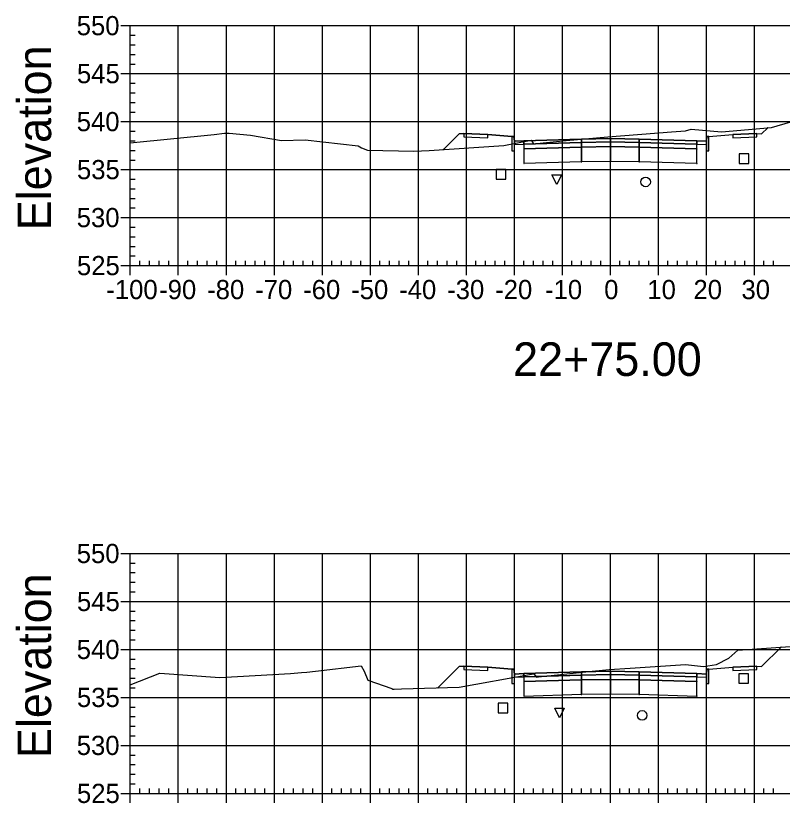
# Model space of a CAD drawing. Extents: x 704834 to 709892, y 372981 to 377533.
# Drawn here: x 707731 to 707890.7, y 376148.8 to 376312.9 of the extents above; entities that cross this region are included whole.
import ezdxf

# ---------------------------------------------------------------- set-up
doc = ezdxf.new("R2010")
doc.units = 0
for name, color, linetype in [('1', 7, 'Continuous'), ('10', 7, 'Continuous'), ('13', 7, 'Continuous'), ('14', 7, 'Continuous'), ('4', 7, 'Continuous'), ('57', 7, 'Continuous'), ('60', 7, 'Continuous'), ('Default_Xsect', 7, 'Continuous'), ('Existing', 7, 'Continuous')]:
    doc.layers.add(name, color=color, linetype=linetype)

msp = doc.modelspace()

# ---------------------------------------------------------------- linework, layer by layer
for points in [[(707886.41, 376288.28), (707887.69, 376289.55)], [(707823.41, 376288.28), (707820.13, 376285)], [(707824.41, 376288.32), (707823.41, 376288.28)], [(707834.41, 376287.72), (707829.41, 376288.12)], [(707875.41, 376287.72), (707880.41, 376288.12)], [(707885.41, 376288.32), (707886.41, 376288.28)], [(707886.41, 376177.26), (707890.47, 376181.31)], [(707823.41, 376177.26), (707818.99, 376172.84)], [(707824.41, 376177.3), (707823.41, 376177.26)], [(707834.41, 376176.7), (707829.41, 376177.1)], [(707875.41, 376176.7), (707880.41, 376177.1)], [(707885.41, 376177.3), (707886.41, 376177.26)]]:
    msp.add_lwpolyline(points)
for points in [[(707829.41, 376288.12), (707824.41, 376288.32), (707824.41, 376287.65), (707829.41, 376287.45)], [(707834.91, 376286.72), (707834.83, 376287.72), (707834.41, 376287.72), (707834.41, 376284.72), (707834.91, 376284.72)], [(707874.91, 376284.72), (707875.41, 376284.72), (707875.41, 376287.72), (707875, 376287.72), (707874.91, 376286.72)], [(707880.41, 376287.45), (707885.41, 376287.65), (707885.41, 376288.32), (707880.41, 376288.12)], [(707836.91, 376286.8), (707834.91, 376286.72), (707834.91, 376286.05), (707836.91, 376286.13)], [(707848.91, 376287.16), (707836.91, 376286.8), (707836.91, 376286.13), (707848.91, 376286.49)], [(707848.91, 376286.49), (707836.91, 376286.13), (707836.91, 376285.13), (707848.91, 376285.49)], [(707848.86, 376286.44), (707848.96, 376286.44), (707848.96, 376286.54), (707848.86, 376286.54)], [(707854.91, 376287.28), (707848.91, 376287.16), (707848.91, 376286.49), (707854.91, 376286.61)], [(707854.91, 376286.61), (707848.91, 376286.49), (707848.91, 376285.49), (707854.91, 376285.61)], [(707854.86, 376286.56), (707854.96, 376286.56), (707854.96, 376286.66), (707854.86, 376286.66)], [(707854.91, 376286.61), (707860.91, 376286.49), (707860.91, 376287.16), (707854.91, 376287.28)], [(707854.91, 376285.61), (707860.91, 376285.49), (707860.91, 376286.49), (707854.91, 376286.61)], [(707860.86, 376286.44), (707860.96, 376286.44), (707860.96, 376286.54), (707860.86, 376286.54)], [(707860.91, 376286.49), (707872.91, 376286.13), (707872.91, 376286.8), (707860.91, 376287.16)], [(707860.91, 376285.49), (707872.91, 376285.13), (707872.91, 376286.13), (707860.91, 376286.49)], [(707872.91, 376286.13), (707874.91, 376286.05), (707874.91, 376286.72), (707872.91, 376286.8)], [(707836.86, 376285.08), (707836.96, 376285.08), (707836.96, 376285.18), (707836.86, 376285.18)], [(707848.91, 376285.49), (707836.91, 376285.13), (707836.91, 376282.13), (707848.91, 376282.49)], [(707848.86, 376285.44), (707848.96, 376285.44), (707848.96, 376285.54), (707848.86, 376285.54)], [(707854.91, 376285.61), (707848.91, 376285.49), (707848.91, 376282.49), (707854.91, 376282.61)], [(707854.86, 376285.56), (707854.96, 376285.56), (707854.96, 376285.66), (707854.86, 376285.66)], [(707854.91, 376282.61), (707860.91, 376282.49), (707860.91, 376285.49), (707854.91, 376285.61)], [(707860.86, 376285.44), (707860.96, 376285.44), (707860.96, 376285.54), (707860.86, 376285.54)], [(707860.91, 376282.49), (707872.91, 376282.13), (707872.91, 376285.13), (707860.91, 376285.49)], [(707872.86, 376285.08), (707872.96, 376285.08), (707872.96, 376285.18), (707872.86, 376285.18)], [(707836.86, 376282.08), (707836.96, 376282.08), (707836.96, 376282.18), (707836.86, 376282.18)], [(707848.86, 376282.44), (707848.96, 376282.44), (707848.96, 376282.54), (707848.86, 376282.54)], [(707854.86, 376282.56), (707854.96, 376282.56), (707854.96, 376282.66), (707854.86, 376282.66)], [(707860.86, 376282.44), (707860.96, 376282.44), (707860.96, 376282.54), (707860.86, 376282.54)], [(707872.86, 376282.08), (707872.96, 376282.08), (707872.96, 376282.18), (707872.86, 376282.18)], [(707829.41, 376177.1), (707824.41, 376177.3), (707824.41, 376176.63), (707829.41, 376176.43)], [(707834.91, 376175.7), (707834.83, 376176.7), (707834.41, 376176.7), (707834.41, 376173.7), (707834.91, 376173.7)], [(707848.91, 376176.14), (707836.91, 376175.78), (707836.91, 376175.11), (707848.91, 376175.47)], [(707854.91, 376176.26), (707848.91, 376176.14), (707848.91, 376175.47), (707854.91, 376175.59)], [(707854.91, 376175.59), (707860.91, 376175.47), (707860.91, 376176.14), (707854.91, 376176.26)], [(707860.91, 376175.47), (707872.91, 376175.11), (707872.91, 376175.78), (707860.91, 376176.14)], [(707874.91, 376173.7), (707875.41, 376173.7), (707875.41, 376176.7), (707875, 376176.7), (707874.91, 376175.7)], [(707880.41, 376176.43), (707885.41, 376176.63), (707885.41, 376177.3), (707880.41, 376177.1)], [(707836.91, 376175.78), (707834.91, 376175.7), (707834.91, 376175.03), (707836.91, 376175.11)], [(707848.91, 376175.47), (707836.91, 376175.11), (707836.91, 376174.11), (707848.91, 376174.47)], [(707848.91, 376174.47), (707836.91, 376174.11), (707836.91, 376171.11), (707848.91, 376171.47)], [(707848.86, 376175.42), (707848.96, 376175.42), (707848.96, 376175.52), (707848.86, 376175.52)], [(707848.86, 376174.42), (707848.96, 376174.42), (707848.96, 376174.52), (707848.86, 376174.52)], [(707854.91, 376175.59), (707848.91, 376175.47), (707848.91, 376174.47), (707854.91, 376174.59)], [(707854.91, 376174.59), (707848.91, 376174.47), (707848.91, 376171.47), (707854.91, 376171.59)], [(707854.86, 376175.54), (707854.96, 376175.54), (707854.96, 376175.64), (707854.86, 376175.64)], [(707854.86, 376174.54), (707854.96, 376174.54), (707854.96, 376174.64), (707854.86, 376174.64)], [(707854.91, 376174.59), (707860.91, 376174.47), (707860.91, 376175.47), (707854.91, 376175.59)], [(707854.91, 376171.59), (707860.91, 376171.47), (707860.91, 376174.47), (707854.91, 376174.59)], [(707860.86, 376175.42), (707860.96, 376175.42), (707860.96, 376175.52), (707860.86, 376175.52)], [(707860.86, 376174.42), (707860.96, 376174.42), (707860.96, 376174.52), (707860.86, 376174.52)], [(707860.91, 376174.47), (707872.91, 376174.11), (707872.91, 376175.11), (707860.91, 376175.47)], [(707860.91, 376171.47), (707872.91, 376171.11), (707872.91, 376174.11), (707860.91, 376174.47)], [(707872.91, 376175.11), (707874.91, 376175.03), (707874.91, 376175.7), (707872.91, 376175.78)], [(707836.86, 376174.06), (707836.96, 376174.06), (707836.96, 376174.16), (707836.86, 376174.16)], [(707872.86, 376174.06), (707872.96, 376174.06), (707872.96, 376174.16), (707872.86, 376174.16)], [(707848.86, 376171.42), (707848.96, 376171.42), (707848.96, 376171.52), (707848.86, 376171.52)], [(707854.86, 376171.54), (707854.96, 376171.54), (707854.96, 376171.64), (707854.86, 376171.64)], [(707860.86, 376171.42), (707860.96, 376171.42), (707860.96, 376171.52), (707860.86, 376171.52)], [(707836.86, 376171.06), (707836.96, 376171.06), (707836.96, 376171.16), (707836.86, 376171.16)], [(707872.86, 376171.06), (707872.96, 376171.06), (707872.96, 376171.16), (707872.86, 376171.16)]]:
    msp.add_lwpolyline(points, close=True)
at = {"layer": '1'}
for points in [[(707843.74, 376277.7), (707842.74, 376279.7), (707844.74, 376279.7)], [(707844.31, 376166.56), (707843.31, 376168.56), (707845.31, 376168.56)]]:
    msp.add_lwpolyline(points, close=True, dxfattribs=at)
at = {"layer": '10'}
for points in [[(707831.14, 376278.83), (707833.14, 376278.83), (707833.14, 376280.83), (707831.14, 376280.83)], [(707831.54, 376167.61), (707833.54, 376167.61), (707833.54, 376169.61), (707831.54, 376169.61)]]:
    msp.add_lwpolyline(points, close=True, dxfattribs=at)
at = {"layer": '13'}
for centre in [(707862.25, 376278.25), (707861.53, 376167.07)]:
    msp.add_circle(centre, 1, dxfattribs=at)
at = {"layer": '14'}
for points in [[(707887.69, 376289.55), (707887.69, 376289.6), (707887.69, 376289.55), (707887.64, 376289.55), (707887.69, 376289.55), (707887.69, 376289.5), (707887.69, 376289.55), (707887.74, 376289.55)], [(707836.91, 376286.8), (707836.91, 376286.85), (707836.91, 376286.8), (707836.86, 376286.8), (707836.91, 376286.8), (707836.91, 376286.75), (707836.91, 376286.8), (707836.96, 376286.8)], [(707854.91, 376287.28), (707854.91, 376287.33), (707854.91, 376287.28), (707854.86, 376287.28), (707854.91, 376287.28), (707854.91, 376287.23), (707854.91, 376287.28), (707854.96, 376287.28)], [(707872.91, 376286.8), (707872.91, 376286.85), (707872.91, 376286.8), (707872.86, 376286.8), (707872.91, 376286.8), (707872.91, 376286.75), (707872.91, 376286.8), (707872.96, 376286.8)], [(707820.13, 376285), (707820.13, 376285.05), (707820.13, 376285), (707820.08, 376285), (707820.13, 376285), (707820.13, 376284.95), (707820.13, 376285), (707820.18, 376285)], [(707890.47, 376181.31), (707890.47, 376181.36), (707890.47, 376181.31), (707890.42, 376181.31), (707890.47, 376181.31), (707890.47, 376181.26), (707890.47, 376181.31), (707890.52, 376181.31)], [(707854.91, 376176.26), (707854.91, 376176.31), (707854.91, 376176.26), (707854.86, 376176.26), (707854.91, 376176.26), (707854.91, 376176.21), (707854.91, 376176.26), (707854.96, 376176.26)], [(707836.91, 376175.78), (707836.91, 376175.83), (707836.91, 376175.78), (707836.86, 376175.78), (707836.91, 376175.78), (707836.91, 376175.73), (707836.91, 376175.78), (707836.96, 376175.78)], [(707872.91, 376175.78), (707872.91, 376175.83), (707872.91, 376175.78), (707872.86, 376175.78), (707872.91, 376175.78), (707872.91, 376175.73), (707872.91, 376175.78), (707872.96, 376175.78)], [(707818.99, 376172.84), (707818.99, 376172.89), (707818.99, 376172.84), (707818.94, 376172.84), (707818.99, 376172.84), (707818.99, 376172.79), (707818.99, 376172.84), (707819.04, 376172.84)]]:
    msp.add_lwpolyline(points, dxfattribs=at)
at = {"layer": '4'}
for points in [[(707881.75, 376282.12), (707883.75, 376282.12), (707883.75, 376284.12), (707881.75, 376284.12)], [(707881.66, 376173.77), (707883.66, 376173.77), (707883.66, 376175.77), (707881.66, 376175.77)]]:
    msp.add_lwpolyline(points, close=True, dxfattribs=at)
at = {"layer": '57'}
for p, q in [((707752.91, 376310.82), (707754.91, 376310.82)), ((707754.91, 376310.82), (707954.91, 376310.82)), ((707754.91, 376260.82), (707754.91, 376310.82)), ((707754.91, 376260.82), (707754.91, 376310.82)), ((707764.91, 376260.82), (707764.91, 376310.82)), ((707774.91, 376260.82), (707774.91, 376310.82)), ((707784.91, 376260.82), (707784.91, 376310.82)), ((707794.91, 376260.82), (707794.91, 376310.82)), ((707804.91, 376260.82), (707804.91, 376310.82)), ((707814.91, 376260.82), (707814.91, 376310.82)), ((707824.91, 376260.82), (707824.91, 376310.82)), ((707834.91, 376260.82), (707834.91, 376310.82)), ((707844.91, 376260.82), (707844.91, 376310.82)), ((707854.91, 376260.82), (707854.91, 376310.82)), ((707864.91, 376260.82), (707864.91, 376310.82)), ((707874.91, 376260.82), (707874.91, 376310.82)), ((707884.91, 376260.82), (707884.91, 376310.82)), ((707754.91, 376308.82), (707755.91, 376308.82)), ((707754.91, 376306.82), (707755.91, 376306.82)), ((707754.91, 376304.82), (707755.91, 376304.82)), ((707754.91, 376302.82), (707755.91, 376302.82)), ((707752.91, 376300.82), (707754.91, 376300.82)), ((707754.91, 376300.82), (707954.91, 376300.82)), ((707754.91, 376298.82), (707755.91, 376298.82)), ((707754.91, 376296.82), (707755.91, 376296.82)), ((707754.91, 376294.82), (707755.91, 376294.82)), ((707754.91, 376292.82), (707755.91, 376292.82)), ((707752.91, 376290.82), (707754.91, 376290.82)), ((707754.91, 376290.82), (707954.91, 376290.82)), ((707754.91, 376288.82), (707755.91, 376288.82)), ((707754.91, 376286.82), (707755.91, 376286.82)), ((707754.91, 376284.82), (707755.91, 376284.82)), ((707754.91, 376282.82), (707755.91, 376282.82)), ((707752.91, 376280.82), (707754.91, 376280.82)), ((707754.91, 376280.82), (707954.91, 376280.82)), ((707754.91, 376278.82), (707755.91, 376278.82)), ((707754.91, 376276.82), (707755.91, 376276.82)), ((707754.91, 376274.82), (707755.91, 376274.82)), ((707754.91, 376272.82), (707755.91, 376272.82)), ((707752.91, 376270.82), (707754.91, 376270.82)), ((707754.91, 376270.82), (707954.91, 376270.82)), ((707754.91, 376268.82), (707755.91, 376268.82)), ((707754.91, 376266.82), (707755.91, 376266.82)), ((707754.91, 376264.82), (707755.91, 376264.82)), ((707754.91, 376262.82), (707755.91, 376262.82)), ((707756.91, 376260.82), (707756.91, 376261.82)), ((707758.91, 376260.82), (707758.91, 376261.82)), ((707760.91, 376260.82), (707760.91, 376261.82)), ((707762.91, 376260.82), (707762.91, 376261.82)), ((707766.91, 376260.82), (707766.91, 376261.82)), ((707768.91, 376260.82), (707768.91, 376261.82)), ((707770.91, 376260.82), (707770.91, 376261.82)), ((707772.91, 376260.82), (707772.91, 376261.82)), ((707776.91, 376260.82), (707776.91, 376261.82)), ((707778.91, 376260.82), (707778.91, 376261.82)), ((707780.91, 376260.82), (707780.91, 376261.82)), ((707782.91, 376260.82), (707782.91, 376261.82)), ((707786.91, 376260.82), (707786.91, 376261.82)), ((707788.91, 376260.82), (707788.91, 376261.82)), ((707790.91, 376260.82), (707790.91, 376261.82)), ((707792.91, 376260.82), (707792.91, 376261.82)), ((707796.91, 376260.82), (707796.91, 376261.82)), ((707798.91, 376260.82), (707798.91, 376261.82)), ((707800.91, 376260.82), (707800.91, 376261.82)), ((707802.91, 376260.82), (707802.91, 376261.82)), ((707806.91, 376260.82), (707806.91, 376261.82)), ((707808.91, 376260.82), (707808.91, 376261.82)), ((707810.91, 376260.82), (707810.91, 376261.82)), ((707812.91, 376260.82), (707812.91, 376261.82)), ((707816.91, 376260.82), (707816.91, 376261.82)), ((707818.91, 376260.82), (707818.91, 376261.82)), ((707820.91, 376260.82), (707820.91, 376261.82)), ((707822.91, 376260.82), (707822.91, 376261.82)), ((707826.91, 376260.82), (707826.91, 376261.82)), ((707828.91, 376260.82), (707828.91, 376261.82)), ((707830.91, 376260.82), (707830.91, 376261.82)), ((707832.91, 376260.82), (707832.91, 376261.82)), ((707836.91, 376260.82), (707836.91, 376261.82)), ((707838.91, 376260.82), (707838.91, 376261.82)), ((707840.91, 376260.82), (707840.91, 376261.82)), ((707842.91, 376260.82), (707842.91, 376261.82)), ((707846.91, 376260.82), (707846.91, 376261.82)), ((707848.91, 376260.82), (707848.91, 376261.82)), ((707850.91, 376260.82), (707850.91, 376261.82)), ((707852.91, 376260.82), (707852.91, 376261.82)), ((707856.91, 376260.82), (707856.91, 376261.82)), ((707858.91, 376260.82), (707858.91, 376261.82)), ((707860.91, 376260.82), (707860.91, 376261.82)), ((707862.91, 376260.82), (707862.91, 376261.82)), ((707866.91, 376260.82), (707866.91, 376261.82)), ((707868.91, 376260.82), (707868.91, 376261.82)), ((707870.91, 376260.82), (707870.91, 376261.82)), ((707872.91, 376260.82), (707872.91, 376261.82)), ((707876.91, 376260.82), (707876.91, 376261.82)), ((707878.91, 376260.82), (707878.91, 376261.82)), ((707880.91, 376260.82), (707880.91, 376261.82)), ((707882.91, 376260.82), (707882.91, 376261.82)), ((707886.91, 376260.82), (707886.91, 376261.82)), ((707888.91, 376260.82), (707888.91, 376261.82)), ((707752.91, 376260.82), (707754.91, 376260.82)), ((707754.91, 376260.82), (707954.91, 376260.82)), ((707754.91, 376260.82), (707954.91, 376260.82)), ((707754.91, 376258.82), (707754.91, 376260.82)), ((707764.91, 376258.82), (707764.91, 376260.82)), ((707774.91, 376258.82), (707774.91, 376260.82)), ((707784.91, 376258.82), (707784.91, 376260.82)), ((707794.91, 376258.82), (707794.91, 376260.82)), ((707804.91, 376258.82), (707804.91, 376260.82)), ((707814.91, 376258.82), (707814.91, 376260.82)), ((707824.91, 376258.82), (707824.91, 376260.82)), ((707834.91, 376258.82), (707834.91, 376260.82)), ((707844.91, 376258.82), (707844.91, 376260.82)), ((707854.91, 376258.82), (707854.91, 376260.82)), ((707864.91, 376258.82), (707864.91, 376260.82)), ((707874.91, 376258.82), (707874.91, 376260.82)), ((707884.91, 376258.82), (707884.91, 376260.82)), ((707752.91, 376200.82), (707754.91, 376200.82)), ((707754.91, 376200.82), (707954.91, 376200.82)), ((707754.91, 376150.82), (707754.91, 376200.82)), ((707754.91, 376150.82), (707754.91, 376200.82)), ((707764.91, 376150.82), (707764.91, 376200.82)), ((707774.91, 376150.82), (707774.91, 376200.82)), ((707784.91, 376150.82), (707784.91, 376200.82)), ((707794.91, 376150.82), (707794.91, 376200.82)), ((707804.91, 376150.82), (707804.91, 376200.82)), ((707814.91, 376150.82), (707814.91, 376200.82)), ((707824.91, 376150.82), (707824.91, 376200.82)), ((707834.91, 376150.82), (707834.91, 376200.82)), ((707844.91, 376150.82), (707844.91, 376200.82)), ((707854.91, 376150.82), (707854.91, 376200.82)), ((707864.91, 376150.82), (707864.91, 376200.82)), ((707874.91, 376150.82), (707874.91, 376200.82)), ((707884.91, 376150.82), (707884.91, 376200.82)), ((707754.91, 376198.82), (707755.91, 376198.82)), ((707754.91, 376196.82), (707755.91, 376196.82)), ((707754.91, 376194.82), (707755.91, 376194.82)), ((707754.91, 376192.82), (707755.91, 376192.82)), ((707752.91, 376190.82), (707754.91, 376190.82)), ((707754.91, 376190.82), (707954.91, 376190.82)), ((707754.91, 376188.82), (707755.91, 376188.82)), ((707754.91, 376186.82), (707755.91, 376186.82)), ((707754.91, 376184.82), (707755.91, 376184.82)), ((707754.91, 376182.82), (707755.91, 376182.82)), ((707752.91, 376180.82), (707754.91, 376180.82)), ((707754.91, 376180.82), (707954.91, 376180.82)), ((707754.91, 376178.82), (707755.91, 376178.82)), ((707754.91, 376176.82), (707755.91, 376176.82)), ((707754.91, 376174.82), (707755.91, 376174.82)), ((707754.91, 376172.82), (707755.91, 376172.82)), ((707752.91, 376170.82), (707754.91, 376170.82)), ((707754.91, 376170.82), (707954.91, 376170.82)), ((707754.91, 376168.82), (707755.91, 376168.82)), ((707754.91, 376166.82), (707755.91, 376166.82)), ((707754.91, 376164.82), (707755.91, 376164.82)), ((707754.91, 376162.82), (707755.91, 376162.82)), ((707752.91, 376160.82), (707754.91, 376160.82)), ((707754.91, 376160.82), (707954.91, 376160.82)), ((707754.91, 376158.82), (707755.91, 376158.82)), ((707754.91, 376156.82), (707755.91, 376156.82)), ((707754.91, 376154.82), (707755.91, 376154.82)), ((707754.91, 376152.82), (707755.91, 376152.82)), ((707756.91, 376150.82), (707756.91, 376151.82)), ((707758.91, 376150.82), (707758.91, 376151.82)), ((707760.91, 376150.82), (707760.91, 376151.82)), ((707762.91, 376150.82), (707762.91, 376151.82)), ((707766.91, 376150.82), (707766.91, 376151.82)), ((707768.91, 376150.82), (707768.91, 376151.82)), ((707770.91, 376150.82), (707770.91, 376151.82)), ((707772.91, 376150.82), (707772.91, 376151.82)), ((707776.91, 376150.82), (707776.91, 376151.82)), ((707778.91, 376150.82), (707778.91, 376151.82)), ((707780.91, 376150.82), (707780.91, 376151.82)), ((707782.91, 376150.82), (707782.91, 376151.82)), ((707786.91, 376150.82), (707786.91, 376151.82)), ((707788.91, 376150.82), (707788.91, 376151.82)), ((707790.91, 376150.82), (707790.91, 376151.82)), ((707792.91, 376150.82), (707792.91, 376151.82)), ((707796.91, 376150.82), (707796.91, 376151.82)), ((707798.91, 376150.82), (707798.91, 376151.82)), ((707800.91, 376150.82), (707800.91, 376151.82)), ((707802.91, 376150.82), (707802.91, 376151.82)), ((707806.91, 376150.82), (707806.91, 376151.82)), ((707808.91, 376150.82), (707808.91, 376151.82)), ((707810.91, 376150.82), (707810.91, 376151.82)), ((707812.91, 376150.82), (707812.91, 376151.82)), ((707816.91, 376150.82), (707816.91, 376151.82)), ((707818.91, 376150.82), (707818.91, 376151.82)), ((707820.91, 376150.82), (707820.91, 376151.82)), ((707822.91, 376150.82), (707822.91, 376151.82)), ((707826.91, 376150.82), (707826.91, 376151.82)), ((707828.91, 376150.82), (707828.91, 376151.82)), ((707830.91, 376150.82), (707830.91, 376151.82)), ((707832.91, 376150.82), (707832.91, 376151.82)), ((707836.91, 376150.82), (707836.91, 376151.82)), ((707838.91, 376150.82), (707838.91, 376151.82)), ((707840.91, 376150.82), (707840.91, 376151.82)), ((707842.91, 376150.82), (707842.91, 376151.82)), ((707846.91, 376150.82), (707846.91, 376151.82)), ((707848.91, 376150.82), (707848.91, 376151.82)), ((707850.91, 376150.82), (707850.91, 376151.82)), ((707852.91, 376150.82), (707852.91, 376151.82)), ((707856.91, 376150.82), (707856.91, 376151.82)), ((707858.91, 376150.82), (707858.91, 376151.82)), ((707860.91, 376150.82), (707860.91, 376151.82)), ((707862.91, 376150.82), (707862.91, 376151.82)), ((707866.91, 376150.82), (707866.91, 376151.82)), ((707868.91, 376150.82), (707868.91, 376151.82)), ((707870.91, 376150.82), (707870.91, 376151.82)), ((707872.91, 376150.82), (707872.91, 376151.82)), ((707876.91, 376150.82), (707876.91, 376151.82)), ((707878.91, 376150.82), (707878.91, 376151.82)), ((707880.91, 376150.82), (707880.91, 376151.82)), ((707882.91, 376150.82), (707882.91, 376151.82)), ((707886.91, 376150.82), (707886.91, 376151.82)), ((707888.91, 376150.82), (707888.91, 376151.82)), ((707752.91, 376150.82), (707754.91, 376150.82)), ((707754.91, 376150.82), (707954.91, 376150.82)), ((707754.91, 376150.82), (707954.91, 376150.82)), ((707754.91, 376148.82), (707754.91, 376150.82)), ((707764.91, 376148.82), (707764.91, 376150.82)), ((707774.91, 376148.82), (707774.91, 376150.82)), ((707784.91, 376148.82), (707784.91, 376150.82)), ((707794.91, 376148.82), (707794.91, 376150.82)), ((707804.91, 376148.82), (707804.91, 376150.82)), ((707814.91, 376148.82), (707814.91, 376150.82)), ((707824.91, 376148.82), (707824.91, 376150.82)), ((707834.91, 376148.82), (707834.91, 376150.82)), ((707844.91, 376148.82), (707844.91, 376150.82)), ((707854.91, 376148.82), (707854.91, 376150.82)), ((707864.91, 376148.82), (707864.91, 376150.82)), ((707874.91, 376148.82), (707874.91, 376150.82)), ((707884.91, 376148.82), (707884.91, 376150.82))]:
    msp.add_line(p, q, dxfattribs=at)
at = {"layer": 'Default_Xsect'}
for points in [[(707820.13, 376285), (707823.41, 376288.28), (707824.41, 376288.32), (707829.41, 376288.12), (707834.41, 376287.72), (707834.83, 376287.72), (707834.91, 376286.72), (707836.91, 376286.8), (707848.91, 376287.16), (707854.91, 376287.28), (707860.91, 376287.16), (707872.91, 376286.8), (707874.91, 376286.72), (707875, 376287.72), (707875.41, 376287.72), (707880.41, 376288.12), (707885.41, 376288.32), (707886.41, 376288.28), (707887.69, 376289.55)], [(707818.99, 376172.84), (707823.41, 376177.26), (707824.41, 376177.3), (707829.41, 376177.1), (707834.41, 376176.7), (707834.83, 376176.7), (707834.91, 376175.7), (707836.91, 376175.78), (707848.91, 376176.14), (707854.91, 376176.26), (707860.91, 376176.14), (707872.91, 376175.78), (707874.91, 376175.7), (707875, 376176.7), (707875.41, 376176.7), (707880.41, 376177.1), (707885.41, 376177.3), (707886.41, 376177.26), (707890.47, 376181.31)]]:
    msp.add_lwpolyline(points, dxfattribs=at)
at = {"layer": 'Existing'}
for points in [[(707754.91, 376286.38), (707772.36, 376288.12), (707774.56, 376288.42), (707774.64, 376288.39), (707775.52, 376288.38), (707779.95, 376287.97), (707786.41, 376286.89), (707791.35, 376287.01), (707802.35, 376285.75), (707803.1, 376285.34), (707804.29, 376284.89), (707813.99, 376284.69), (707817.19, 376284.8), (707832.69, 376285.87), (707838.38, 376286.97), (707838.58, 376286.72), (707838.88, 376286.21), (707845.67, 376286.9), (707854.35, 376287.64), (707867.66, 376288.66), (707870.59, 376288.92), (707871.77, 376289.28), (707878.06, 376288.71), (707888.49, 376289.62), (707892.48, 376290.77)], [(707754.91, 376173.46), (707761.04, 376175.86), (707773.54, 376174.96), (707788.27, 376175.81), (707790.6, 376175.99), (707791.67, 376176.11), (707793.45, 376176.31), (707803, 376177.42), (707803.64, 376176.29), (707804.37, 376174.45), (707809.37, 376172.65), (707809.61, 376172.56), (707809.88, 376172.55), (707811.4, 376172.6), (707823.4, 376172.97), (707838.07, 376175.6), (707838.94, 376175.77), (707839.52, 376175.07), (707839.52, 376175.06), (707839.93, 376175.11), (707850.43, 376176.19), (707854.63, 376176.62), (707859.02, 376176.9), (707870.58, 376177.7), (707874.34, 376177.24), (707876.99, 376177.66), (707879.62, 376179), (707881.44, 376180.69), (707896.3, 376181.71)]]:
    msp.add_lwpolyline(points, dxfattribs=at)

# ---------------------------------------------------------------- texts
at = {"layer": '1'}
msp.add_text('22+75.00', height=7, dxfattribs=at).set_placement((707834.64, 376237.82))
at = {"layer": '14'}
for p in [(707824.38, 376288.27), (707885.38, 376288.27), (707824.38, 376287.6), (707829.38, 376287.4), (707880.38, 376287.4), (707885.38, 376287.6), (707824.38, 376177.25), (707824.38, 376176.58), (707829.38, 376176.38), (707880.38, 376176.38), (707885.38, 376177.25), (707885.38, 376176.58)]:
    msp.add_text('+', height=0.1, dxfattribs=at).set_placement(p)
at = {"layer": '57'}
for s, p in [('550', (707743.74, 376308.82)), ('545', (707743.79, 376298.82)), ('540', (707743.74, 376288.82)), ('535', (707743.79, 376278.82)), ('530', (707743.74, 376268.82)), ('525', (707743.79, 376258.82)), ('-100', (707749.9, 376253.82)), ('-90', (707760.91, 376253.82)), ('-80', (707770.91, 376253.82)), ('-70', (707780.91, 376253.82)), ('-60', (707790.91, 376253.82)), ('-50', (707800.91, 376253.82)), ('-40', (707810.91, 376253.82)), ('-30', (707820.91, 376253.82)), ('-20', (707830.91, 376253.82)), ('-10', (707841.3, 376253.82)), ('0', (707853.62, 376253.82)), ('10', (707862.61, 376253.82)), ('20', (707872.22, 376253.82)), ('30', (707882.22, 376253.82)), ('550', (707743.74, 376198.82)), ('545', (707743.79, 376188.82)), ('540', (707743.74, 376178.82)), ('535', (707743.79, 376168.82)), ('530', (707743.74, 376158.82)), ('525', (707743.79, 376148.82))]:
    msp.add_text(s, height=4, dxfattribs=at).set_placement(p)
at = {"layer": '60'}
for p in [(707738.41, 376268.18), (707738.41, 376158.18)]:
    msp.add_text('Elevation', height=7, rotation=90, dxfattribs=at).set_placement(p)

doc.saveas('drawing.dxf')
